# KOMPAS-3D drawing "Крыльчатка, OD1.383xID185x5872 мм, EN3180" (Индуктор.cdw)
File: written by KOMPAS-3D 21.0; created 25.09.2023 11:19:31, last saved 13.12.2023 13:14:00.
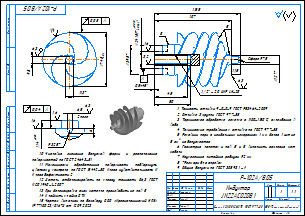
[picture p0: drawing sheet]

Sheet 1: A3, landscape

Document properties: Автор: Constr2; Знак неуказанной шероховатости: 6; Полное имя файла: Колесо большое.m3d

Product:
- Component: Отверстие  | additional columns: MF 13x1,5
- Part/product: Крыльчатка, OD1.383xID185x5872 мм  | designation EN3180
    Материал: Сталь 07Х18Н10Г2С2М2Л ГОСТ 977-88 (density 7850 kg/m3)
    Масса: 1238.171927

Title block, sheet 1: Наименование: Индуктор / JN22AC02DB1; designation: P-102A/В.05; Материал: Сталь 12Х18Н12М3ТЛ ГОСТ 977-88; Масса: 1; scale: 1:1; Количество листов документа: 1; organisation: ООО "Точная технодинамика"; Форматы листов документа: A3; stored path: D:\Максимов\Шаблон чертежа.cdt; Разработал: Дущенко; Т. контр.: Серков; Н. контр.: Юсупов; Утвердил: Елагин

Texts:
  Сфера
  индуктор  готово.jpg
  cil1_ex_ISO 724 fine.xml
  Метрическая резьба с мелким шагом ISO 724 (DIN 13, BS 3643, ANSI/ASME B1.13M) (MF)
  MF 13x1,5
  Отверстие
Dimensions and other numbers on the sheet: 11,3; 9,8; 74,5; 6; 6,5; 2 паза; 3,25; 6,3; 45; 50; 118,5; 11,5; 7,5; 12,7; 24,15; 39,5; 1,6; 11,4; 0,04; 1/2" - 20 UNF LH-2В; 3,2; 0,5; 0,08; 107; 1; 1:1

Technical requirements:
  Точность отливки 9-0-0-9 ГОСТ Р53464-2009.
  Отливка 3 группы ГОСТ 977-88.
  Термическая обработка: закалка с 1100-1150°С, охлаждение в
  воде.
  Технические требования к отливке по ГОСТ 977-88.
  Раковины поры с наибольшим измерением 1 мм более 1 шт на
  5 см 2  не допускается.
  Геометрию лопаток и пов.  Б  и  В  выполнить согласно мат.
  модели.
  Неуказанные литейные радиусы R2 мм.
  *Размеры для справок.
  Общие допуски по ГОСТ 30893.1 - f.
  Числовые значения допусков формы и расположения
  поверхностей по ГОСТ 24643-81.
  Механически обработанные поверхности подвергнуть
  цветному контролю по ГОСТ 18442-80. Класс чувствительности II.
  Класс дефектности 2.
  Деталь отбалансировать по классу точности G6,3 ГОСТ
  ИСО 1940-1-2007.
  При балансировке съем металла производить на пов.  В .
  Клеймить клеймо ОТК.
  Чертеж выполнен по договору ООО «Красноленинский НПЗ»
  №7710023/0167Д от 12.09.2023.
